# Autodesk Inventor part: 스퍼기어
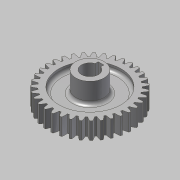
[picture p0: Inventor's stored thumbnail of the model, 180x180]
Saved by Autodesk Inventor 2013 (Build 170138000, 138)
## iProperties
Created: 2013-08
Part Number: 스퍼기어
Material: 강
Document SubType Name: Modeling
Designer: 한국산업디자인학원
Categories: <?xml version="1.0" encoding="UTF-16"?> <MemberInstance><Categories><FamilyTemplate><FamilyTemplateParameter ValueType="xs:double" Id="1" ObjectReferenceKey="da
Density: 1 g/cm^3
CustomPartVersion: 1
Author: 한국산업디자인학원
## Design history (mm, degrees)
sketch "Sketch1"
  geometry: C1 r 37 at (0, 0)
  constraints: 1 centre point
  dimensions: "d0" = 74 diameter of C1 (= da_da)
extrude "Extrusion1" new body sketch "Sketch1" distance "d1" = 15 (= da_b); taper "d2" = 0 deg
workplane "Work Plane2"
feature "피치 지름" dims "d4" = 10, "d5" = 0
workplane "Work Plane8"
workplane "Work Plane9"
feature "스퍼 기어" dims "da_b" = 15, "da_d" = 70, "da_aw" = 70, "da_da" = 74, "da_df" = 65, "da_dw" = 70, angle "da_beta" = 0 deg, "da_lefttooth" = 0, "da_righttooth" = 0
sketch "스케치3"
  geometry: L1 (0, 28)-(0, -3); L2 (12.5, 10)-(27.5, 10); L3 (27.5, 10)-(27.5, 15); L4 (27.5, 15)-(12.5, 15); L5 (12.5, 15)-(12.5, 10); L6 (32.426, 0)-(36.991, 0) reference; L7 (12.5, 0)-(27.5, 0); L8 (27.5, 0)-(27.5, 5); L9 (27.5, 5)-(12.5, 5); L10 (12.5, 5)-(12.5, 0); L11 (36.991, 15)-(32.426, 15) reference; 1 further point
  constraints: 18 end point, 4 parallel, 2 horizontal, 2 perpendicular, 1 vertical, 1 vertical alignment
  dimensions: "d49" = 31 distance of L1.start L1.end; "d51" = 3 distance of point (0, 0) L1.end; "d52" = 55 diameter of L3 L1; "d53" = 25 diameter of L5 L1; "d54" = 5 distance between parallel lines of L4 L2; "d55" = 15 distance between parallel lines of L6 L4; "d56" = 5 distance of L7.end L8.end; "d57" = 55 diameter of L8 L1; "d58" = 25 diameter of L10 L1; "d59" = 15 distance between parallel lines of L11 L7
revolve "회전1" sketch "스케치3" stored, may be unused: angle "d60" = 90 deg
sketch "스케치4"
  geometry: L1 (-2.5, 9.8)-(2.5, 9.8); L2 (2.5, 9.8)-(2.5, 7.071); L3 (-2.5, 9.8)-(-2.5, 7.071); C1 r 12.5 at (0, 0) reference; A1 r 7.5 centre (0, 0) between (2.5, 7.071) and (-2.5, 7.071); 1 further point
  constraints: 6 end point, 2 point on circle, 1 centre point, 1 coincident, 1 horizontal, 1 midpoint, 1 parallel, 1 perpendicular, 1 vertical alignment
  dimensions: "d61" = 15 diameter of A1; "d63" = 5 distance of L1.start L1.end; "d64" = 17.3 dimension on A1 L1
extrude "돌출2" join sketch "스케치4" distance "d65" = 3; taper "d67" = 0 deg; dims "d66" = 28, "d68" = 0
extrude "돌출3" cut sketch "스케치4" distance "d69" = 3; taper "d71" = 0 deg; dims "d70" = 28, "d72" = 0
fillet "모깎기1" dims "d73" = 3
body "Solid1"
sketch "Sketch2"
  geometry: C1 r 37 at (0, 0) reference; C2 r 35 at (0, 0)
  constraints: 1 centre point, 1 coincident
  dimensions: "d3" = 70 diameter of C2 (= da_dw)
body "Srf1"
other parameters: "d17" = 0, "d34" = 0.8976 (computed from da_z), "d39" = 0, "d41" = 0, "d47" = 0, "d48" = 0
